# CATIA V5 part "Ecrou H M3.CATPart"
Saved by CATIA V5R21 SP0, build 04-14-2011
Part number: Ecrou H M3
Material "Acier": density 7860 kg/m3, Young's modulus 2e+11 Pa, Poisson ratio 0.266, thermal expansion 1.17e-05 1/K
Bounding box of the stored display mesh (mm): x -2.5 to 2.5, y -2.887 to 2.887, z 0 to 2
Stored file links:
  C:\Users\Olivier\Desktop\redaction CATIA (local)\CATIA\DONNEES\Exercice mise en plan 2 (Pompe de ventilation)\Pompe de ventilation (Product inclus)\Ecrou H M3.CATPart
  C:\Program Files\Dassault Systemes\B21\win_b64\startup\materials\French\Catalog.CATMaterial
  C:\Users\Olivier\Desktop\redaction CATIA (local)\CATIA\DONNEES\Exercice mise en plan 2 (Pompe de ventilation)\Pompe de ventilation (Product inclus)\CATIA_EnvironmentMap_Satin_512x512.jpg
  C:\Users\Olivier\Desktop\redaction CATIA (local)\pompe à moteur de ventilation refait\Pompe_a_moteur_de_ventilation.CATProduct
  C:\Users\Olivier\Desktop\redaction CATIA (local)\pompe à moteur de ventilation refait\Ecrou a collerette M5.CATPart
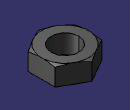
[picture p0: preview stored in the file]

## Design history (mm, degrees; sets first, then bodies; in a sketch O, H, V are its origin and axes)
Body1 (main body), material "Acier"
  Sketch1 on xy-plane, origin (0, 0, 0), H (1, 0, 0), V (0, 1, 0)
    circle A1 centre (0, 0) radius 1.5
    point P1 (2.5, -1.4434)
    point P2 (2.5, 1.4434)
    point P3 (0, 2.8868)
    point P4 (-2.5, 1.4434)
    point P5 (-2.5, -1.4434)
    point P6 (0, -2.8868)
    point P7 (2.5, 0)
    line L1 (2.5, -1.4434) -> (2.5, 1.4434)
    line L2 (2.5, 1.4434) -> (0, 2.8868)
    line L3 (0, 2.8868) -> (-2.5, 1.4434)
    line L4 (-2.5, 1.4434) -> (-2.5, -1.4434)
    line L5 (-2.5, -1.4434) -> (0, -2.8868)
    line L6 (0, -2.8868) -> (2.5, -1.4434)
    construction line L7 (0, 0) -> (2.5, 0)
    construction circle A2 centre (0, 0) radius 2.8868
    construction arc A3 centre (-2.5, -1.4434) radius 2.8868 from (-2.5, 1.4434) to (0, -2.8868) cw
    construction arc A4 centre (2.5, 1.4434) radius 2.8868 from (0, 2.8868) to (2.5, -1.4434) ccw
    distance L1 L4 = 5
    horizontal: L7 H
    coincidence: A2 P1, A2 P2, A2 P3, A2 P4, A2 P5, A2 P6, A3 O, A4 O
    midpoint: P7 L1
  Pad1: profile Sketch1, direction (0, 0, 1), length 2
  Sketch2 on yz-plane, origin (0, 0, 0), H (0, 1, 0), V (0, 0, 1)
    line L1 (2.4595, 2.0276) -> (2.9071, 2.0276)
    point P1 (2.4595, 2.0276)
    line L2 (2.9071, 2.0276) -> (2.9071, 1.8177)
    line L3 (2.9071, 1.8177) -> (2.4663, 2.0244)
    horizontal: L1 H
    vertical: L2 V
    coincidence: L3 P1
  Groove1: profile Sketch2, axis Sketch2.V, angle 360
